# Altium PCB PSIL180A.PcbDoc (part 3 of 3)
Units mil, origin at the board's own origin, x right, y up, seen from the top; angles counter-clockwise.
Board outline 4350 x 4350 mil, 4 copper layers (L1-Top Layer, L2-GND, L3-GND/SIG, L4-Bottom Layer), stack 60.02 mil thick; 134 components, 52 nets, 287 pads, 1110 vias.
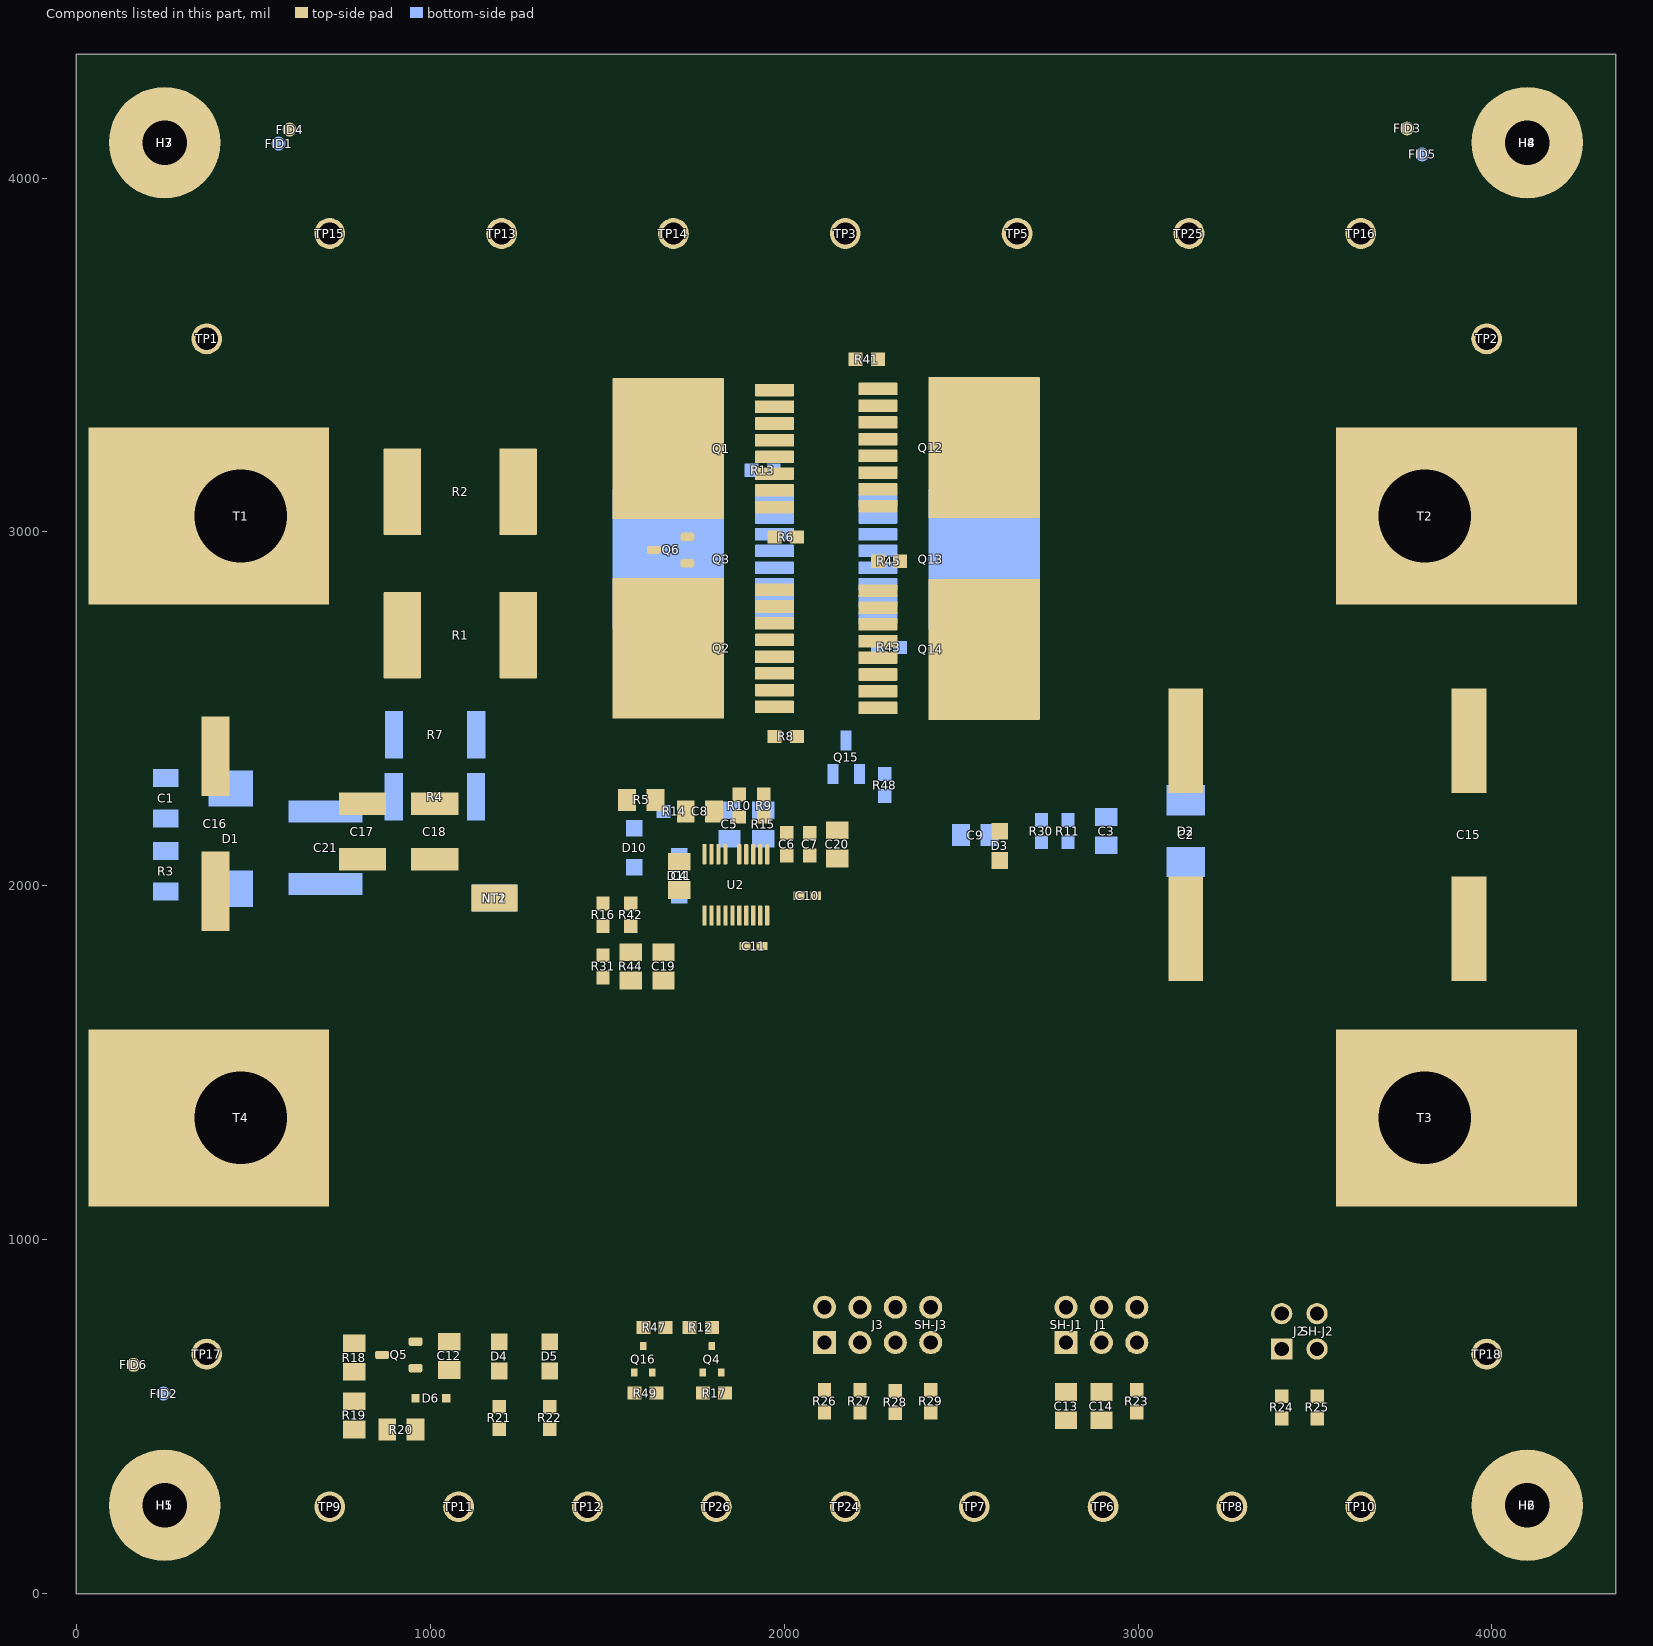
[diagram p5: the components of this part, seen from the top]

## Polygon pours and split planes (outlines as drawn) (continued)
GND on L4-Bottom Layer "L1-Top Layer-GND" (solid, remove dead copper, pour order 158): 4274.08,893.13 4318.92,848.29 4318.92,100.57 4256.14,37.79 1954.09,37.79 135.88,37.79 47.55,126.12 47.55,816.08 124.6,893.13
GND on L4-Bottom Layer "L2-GND-GND 1" (solid, remove dead copper, pour order 42): 1229.29,1736.51 1229.29,1908.33 1208.39,1929.23 1208.39,2001.67 1229.29,2022.57 1229.29,2105.78 1275.44,2151.93 1509.75,2151.93 1527.77,2133.91 1527.77,2027.73 1618.65,1936.85 1745.14,1936.85 1798.97,1990.68 1798.97,2147.17 1818.65,2167.01 1879.17,2167.01 1897.46,2148.72 1897.46,2106.89 1952.45,2051.9 2317.87,2051.9 2372.25,2106.28 2372.25,2175.91 2380.57,2184.23 2482.44,2184.23 2514.74,2151.93 2514.74,1788.89 2345.54,1619.69 1346.11,1619.69
PGND on L2-GND "L2-GND-GND 2" (solid, remove dead copper, pour order 208): 4244.3,2180.52 2596,2180.52 2571.47,2155.99 2571.47,1686.32 3327.83,929.96 4267.68,929.96 4316.91,979.19 4316.91,2107.91
GND on L2-GND "L2-GND-GND" (solid, remove dead copper, pour order 206): 1229.29,2120.26 1229.29,1012.12 1110.07,892.9 124.37,892.9 47.55,816.08 47.55,126.12 135.88,37.79 4256.14,37.79 4318.92,100.57 4318.92,848.29 4274.08,893.13 3278.15,893.13 2514.74,1656.54 2514.74,2150.38 2484.89,2180.23 2363.52,2180.23 2263.85,2080.56 1785.16,2080.56 1648.83,1944.23 1619.01,1944.23 1597.84,1965.4 1597.84,2161.01 1578.62,2180.23 1289.26,2180.23
no net on L2-GND "L2-GND-No Net" (solid, remove dead copper, pour order 204): 1382.07,2094.92
NetQ15_3 on L2-GND "L2-GND-NetQ15_5" (solid, remove dead copper, pour order 182): 1283.87,2409.16 1182.12,2409.16 1155.82,2382.86 1155.82,2229.86 1174.86,2210.96 1963.29,2210.96 2004.8,2252.47 2004.8,2314.47 2030.72,2340.39 2140.03,2340.39 2167.18,2367.54 2167.18,2458.44 2148.33,2477.29 1870.09,2477.29 1801.96,2409.16
VIN on L2-GND "L1-Top Layer-VIN" (solid, remove dead copper, pour order 180): 966.32,2209.69 1033.92,2277.29 1033.92,3466.52 897.93,3602.51 92.44,3602.51 33.33,3543.4 33.33,2273.62 97.26,2209.69 146.95,2209.69 153.96,2202.68 172.22,2202.68 179.43,2209.69 467.81,2209.69
CS- on L2-GND "L1-Top Layer-CS-" (solid, remove dead copper, pour order 178): 1148.84,2503.42 1148.84,3550.99 1054.75,3645.08 92.7,3645.08 33.33,3704.45 33.33,4226.37 121.63,4314.67 2747.98,4314.67 2824.14,4238.51 2824.14,3679.98 2753.48,3609.32 2003.28,3609.32 1878.79,3484.83 1878.79,2526.63 1795,2444.06 1208.2,2444.06
VOUT on L2-GND "L1-Top Layer-VOUT 1" (solid, remove dead copper, pour order 176): 2374.5,2241.54 2386.05,2253.09 2386.05,3519.16 2449.22,3582.33 2764.55,3582.33 2851.07,3668.85 2851.07,4246.52 2916.44,4311.89 4236.52,4311.89 4316.07,4232.34 4316.07,2277.74 4247.12,2208.79 2411.97,2208.79 2392.58,2228.5 2379.78,2228.5 2374.5,2233.78
SRC on L2-GND "L1-Top Layer-VIN" (solid, remove dead copper, pour order 138): 2152.33,2323.24 2185.31,2356.22 2185.31,2466.32 2156.89,2495.12 1943.44,2495.12 1910.92,2527.64 1910.92,3426.1 1927.58,3442.75 2298.85,3442.75 2361.38,3380.22 2361.29,2252.16 2246.25,2137.12 2038.48,2137.12 2023.93,2151.67 2023.93,2309.25 2037.92,2323.24
PGND on L2-GND "L1-Top Layer-PGND 1" (solid, remove dead copper, pour order 172): 1036.54,2180.52 1142.08,2074.98 1142.08,1080.24 991.8,929.96 131.98,929.96 33.33,1028.61 33.33,2081.38 132.47,2180.52
VOUT on L3-GND/SIG "L3-GND/SIG-VOUT" (solid, pour order 196): 3300.64,971.83 2641.74,971.83 2234.07,1379.5 2234.07,1999.37 2363.43,2128.73 2363.43,2329.59 2384.56,2351.3 2384.56,2479.18 2458.13,2552.75 2458.13,3076.46 2388.65,3145.94 2388.65,3559.57 2449.24,3620.16 4051.32,3620.16 4302.95,3368.53 4302.95,101.16 4239.02,37.23 3727.29,37.23 3679.56,84.96 3679.56,706.75 3537.69,848.62 3423.85,848.62
SRC on L3-GND/SIG "L3-GND/SIG-SRC 1" (solid, pour order 192): 2041.93,2780.57 2030.86,2769.5 2030.86,2561.32 2088.86,2503.32 2200.89,2503.32 2229.31,2531.74 2229.31,2763.73 2212.07,2780.97
SRC on L3-GND/SIG "L3-GND/SIG-SRC 2" (solid, pour order 190): 2040.19,3426.79 2031.26,3417.86 2031.26,3037.17 2106.57,2961.86 2106.57,2892.52 2120.3,2878.79 2223.96,2878.79 2258.25,2913.08 2258.25,3390.08 2221.7,3426.63
no net on L3-GND/SIG "L3-GND/SIG-No Net" (solid, pour order 188): 2649.11,3832.49
VIN on L3-GND/SIG "L3-GND/SIG-VIN" (solid, remove dead copper, pour order 186): 969.08,2233.38 1008.92,2233.38 1033.92,2258.38 1033.92,2285.42 1033.92,3466.52 897.57,3602.87 92.44,3602.51 31.88,3541.95 31.88,2277.94 76.44,2233.38
CS- on L3-GND/SIG "L1-Top Layer-CS-" (solid, remove dead copper, pour order 146): 1453.58,740.68 995.48,282.58 995.48,185.17 897.21,86.9 496.18,84.46 121.19,84.46 43.34,162.31 43.34,2078.48 128.22,2163.36 1038.24,2163.36 1148.84,2273.96 1148.84,2901.2 1148.84,3462.83 1239.13,3553.12 1802.9,3553.12 1839.68,3516.34 1839.68,3439.24 1650.14,3249.7 1650.14,2063.84 1650.24,1973.86 1453.58,1777.2

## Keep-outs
Keep-Out Layer:
  text ".Layer_Name" at -73,-825.99 h60

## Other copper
L1-Top Layer:
  pour cut-out: 160.36,708.74 cw(c160.36,648.74) 220.36,648.74 cw(c160.36,648.74) 160.36,588.74 cw(c160.36,648.74) 100.36,648.74 cw(c160.36,648.74)
  pour cut-out: 3760.04,4200.03 cw(c3760.04,4140.03) 3820.04,4140.03 cw(c3760.04,4140.03) 3760.04,4080.03 cw(c3760.04,4140.03) 3700.04,4140.03 cw(c3760.04,4140.03)
  pour cut-out: 602.83,4077.04 cw(c602.83,4137.04) 542.83,4137.04 cw(c602.83,4137.04) 602.83,4197.04 cw(c602.83,4137.04) 662.83,4137.04 cw(c602.83,4137.04)
  region net VIN: 1602.33,2145.88 1612.28,2135.93 1628.38,2135.93 1635.68,2143.23 1635.68,2169.78 1628.32,2177.14 1608.95,2177.14 1602.32,2170.51
  region net DIODE: 1949.73,1947.45 1946.62,1944.34 1946.62,1869.6 1921.43,1844.41 1921.43,1817.93 1924.13,1815.23 1982.41,1815.23 1996.87,1829.69 1996.87,1943.36 1992.78,1947.45
  region net NetC19_1: 1695.04,1802.2 1695.04,1789.96 1692.2,1787.12 1534.82,1787.12 1532.53,1789.41 1532.53,1899.02 1541.25,1907.74 1603.55,1907.74 1641.88,1946.07 1778.98,1946.07 1780.97,1944.08 1780.97,1888.13
  region net GND: 2506.7,2180.23 2514.74,2172.19 2514.74,1864.95 2500.78,1850.99 2385.83,1850.99 2357.48,1879.34 2357.48,2156.1 2381.61,2180.23
  region net NetC4_1: 1762.41,2043.26 1673.57,2043.26 1672.49,2044.34 1672.49,2095.42 1698.14,2121.07 1777.12,2121.07 1780.96,2117.23 1780.96,2061.81
  pour cut-out: 2033.05,2392.05
  region net SRC: 1939.44,2162.71 1974.77,2162.71 2019.81,2207.74 2087.54,2207.74 2093.53,2201.76 2093.53,2131.32 2091.41,2129.29 1925.8,2129.29 1918.83,2122.32 1918.83,2061.95 1917.85,2060.97 1908.02,2060.97 1907.06,2061.93 1907.05,2130.32
  region net CS-: 1130.03,3127.1 1132.46,3124.67 1132.46,3112.73 1125.05,3105.32 1117.55,3105.32 1114.38,3108.49 1114.38,3124.32 1117.16,3127.1
  region net VIN: 1049.49,3127.1 1047.06,3124.67 1047.06,3112.73 1054.47,3105.32 1061.97,3105.32 1065.14,3108.49 1065.14,3124.32 1062.36,3127.1
  region: 1848.83,2930.39
  region net CS-: 1123.13,2702.97 1123.13,2697.63 1117.55,2692.05 1099.77,2692.05 1098.62,2693.2 1098.62,2725.27 1101.18,2727.83 1115.52,2727.83 1123.13,2720.22
  region net VIN: 1052.05,2714.88 1052.05,2720.22 1057.63,2725.8 1075.41,2725.8 1076.56,2724.65 1076.56,2692.58 1074,2690.02 1059.66,2690.02 1052.05,2697.63
  region net GND: 2070.65,1983.87 2116,2029.22 2116,2101.34 2122.19,2107.53 2200.9,2107.53 2213.27,2095.16 2213.27,1937.9 2132.21,1857.86 2076.42,1857.86 2070.65,1863.63
  region: 755.75,652.2
  region net GND: 1879.45,1888.74 1879.45,1882.84 1890.67,1871.62 1890.75,1858.72 1907.72,1841.75 1907.72,1813.76 1899.88,1805.92 1868.67,1805.92 1859.85,1814.74 1859.85,1872.26 1867.72,1880.13 1867.72,1973.97 1859.41,1982.28 1837.04,1982.28 1813.83,1959.07 1758.54,1959.07 1674.95,1959.07 1670.69,1963.33 1670.69,2011.95 1674.5,2015.76 1758.09,2015.76 1775.39,1998.46 1802.17,1998.46 1816.05,2012.34 1867.36,2012.34 1879.45,2000.25
  region net GND: 2748.09,500.79 2764.56,519.01 2949.86,519.01 2965.61,534.76 3022.69,534.76 3036.47,520.98 3036.47,414.68 3024.94,403.14 2760.88,403.14 2748.09,415.94
  region net GND: 1053.23,504.21 1032.21,525.23 1032.21,596.1 1019.41,608.89 1019.41,656.13 1023.35,660.07 1085.38,660.07 1104.06,641.4 1104.06,512.08 1096.18,504.21
  region net GND: 2453.24,521.96 2461.12,514.09 2461.12,444.57 2447.8,430.43 2092.02,430.43 2079.23,443.22 2079.23,518.75 2097.73,535.74 2439.46,535.74
  region net GND: 3366.01,506.95 3373,517.78 3535.3,517.78 3546.13,506.95 3546.13,420.51 3538.08,412.46 3375.15,412.46 3366.01,421.6
  region: 2031.36,787.48
  text ".Layer_Name" at -73,-825.99 h60
L2-GND:
  text ".Layer_Name" at -73,-825.99 h60
L3-GND/SIG:
  region net GATE: 1991.7,2930.73 1986.53,2935.9 1969.29,2935.9 1964.65,2931.26 1956.31,2931.26 1951.24,2936.33 1923.39,2936.33 1914.08,2926.85 1914.08,2878.36 1898.54,2862.82 1898.54,2824.12 1903.26,2819.4 1912.11,2819.4 1918.18,2813.33 1918.18,2780.51 1923.11,2775.58 1939.94,2775.58 1947.63,2783.27 1947.63,2806.15 1955.97,2814.49 1969.43,2814.49 1985.93,2797.99 2009.55,2797.79 2020.09,2808.33 2020.09,2824.37 1998.43,2846.03 1998.43,2852.32 2003.9,2857.79 2003.9,2883.11 1991.7,2895.31
  region net GATE: 2156.71,2262.99
  text ".Layer_Name" at -70,-835.99 h60
L4-Bottom Layer:
  pour cut-out: 246.92,625.59 ccw(c246.92,565.59) 186.92,565.59 ccw(c246.92,565.59) 246.92,505.59 ccw(c246.92,565.59) 306.92,565.59 ccw(c246.92,565.59)
  pour cut-out: 3802.99,4126.92 ccw(c3802.99,4066.92) 3742.99,4066.92 ccw(c3802.99,4066.92) 3802.99,4006.92 ccw(c3802.99,4066.92) 3862.99,4066.92 ccw(c3802.99,4066.92)
  pour cut-out: 571.68,4037.21 ccw(c571.68,4097.21) 631.68,4097.21 ccw(c571.68,4097.21) 571.68,4157.21 ccw(c571.68,4097.21) 511.68,4097.21 ccw(c571.68,4097.21)
  text ".Layer_Name" at -73,-825.99 h60
Multi-Layer:
  pour cut-out: 1687.36,3749.34 cw(c1687.36,3843.34) 1593.36,3843.34 cw(c1687.36,3843.34) 1687.36,3937.34 cw(c1687.36,3843.34) 1781.36,3843.34 cw(c1687.36,3843.34)
  pour cut-out: 1201.8,3749.34 cw(c1201.8,3843.34) 1107.8,3843.34 cw(c1201.8,3843.34) 1201.8,3937.34 cw(c1201.8,3843.34) 1295.8,3843.34 cw(c1201.8,3843.34)
  pour cut-out: 716.24,3749.34 cw(c716.24,3843.34) 622.24,3843.34 cw(c716.24,3843.34) 716.24,3937.34 cw(c716.24,3843.34) 810.24,3843.34 cw(c716.24,3843.34)
  pour cut-out: 3629.6,3749.34 cw(c3629.6,3843.34) 3535.6,3843.34 cw(c3629.6,3843.34) 3629.6,3937.34 cw(c3629.6,3843.34) 3723.6,3843.34 cw(c3629.6,3843.34)
  pour cut-out: 3915,250 ccw(c4100,250) 4100,65 ccw(c4100,250) 4285,250 ccw(c4100,250) 4100,435 ccw(c4100,250)
  pour cut-out: 3915,4100 ccw(c4100,4100) 4100,3915 ccw(c4100,4100) 4285,4100 ccw(c4100,4100) 4100,4285 ccw(c4100,4100)
  pour cut-out: 65,250 ccw(c250,250) 250,65 ccw(c250,250) 435,250 ccw(c250,250) 250,435 ccw(c250,250)
  pour cut-out: 65.73,4102.58 ccw(c250.73,4102.58) 250.73,3917.58 ccw(c250.73,4102.58) 435.73,4102.58 ccw(c250.73,4102.58) 250.73,4287.58 ccw(c250.73,4102.58)

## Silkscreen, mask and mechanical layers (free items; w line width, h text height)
Top Overlay:
  drawing of 50 lines, arcs and shapes, not listed
  text "VIN" at 534.62,3375.26 h60
  text "VOUT" at 3634.96,3375.67 h60
  text "Max current 50A" at 49.31,2676 h50
  text "Max current 50A" at 3507.94,2676 h50
  text "11" at 1923.67,2124.51 h35
  text "20" at 1704.55,2121.27 h35
  text "10" at 1981.07,1864.1 h35
  text "Max current 50A" at 49.31,1678.37 h50
  text "Max current 50A" at 3507.94,1642.29 h50
  text "'.PRJ_Title'" at 1318.46,1489.55 h70
  text "'.PRJ_Number''.PCB_Rev'" at 1318.46,1371.02 h70
  text "TMR" at 2872.34,877.69 h35
  text "IWRN" at 2190.74,875.76 h35
  text "PGND" at 263.93,873.59 h60
  text "IMON" at 3404.39,867.73 h35
  text "PGND" at 3822.51,855.14 h60
  text "FLT_I/" at 1272.78,577.46 h30 r90
  text "FLT_T/" at 1415.81,577.46 h30 r90
  text ".Layer_Name" at -73,-825.99 h60
Bottom Overlay:
  region: 2213.65,2282.14 2236.91,2258.88 2190.45,2258.88
  text ".Layer_Name" at -73,-825.99 h60
Top Paste:
  text ".Layer_Name" at -73,-825.99 h60
Bottom Paste:
  text ".Layer_Name" at -73,-825.99 h60
Top Solder:
  text ".Layer_Name" at -73,-825.99 h60
  text ".Layer_Name" at -73,-825.99 h60
Bottom Solder:
  text ".Layer_Name" at -73,-825.99 h60
Drill Guide:
  text ".Layer_Name" at -73,-825.99 h60
M1 Board Outline:
  the board outline again, w10
  text ".Layer_Name" at -62,-837.5 h60
M2 Board Dimensions:
  rectangle: -525,-367.5 -150,-242.5
  rectangle: -650,-242.5 -525,-117.5
  lines w7: -650,-242.5 350,-242.5 ; -525,-367.5 -525,-117.5 ; -400,-367.5 -400,-117.5 ; -150,-367.5 -150,-117.5 ; 100,-367.5 100,-117.5 ; -650,-367.5 -650,-117.5 350,-117.5 350,-367.5 -650,-367.5
  text ".Layer_Name" at -70,-835.99 h60
M3 3D STEP Top:
  text ".Layer_Name" at -73,-825.99 h60
M4 3D STEP Bottom:
  text ".Layer_Name" at -73,-825.99 h60
M5 Assembly Top:
  lines w10: -942,-897.67 5658,-897.67 ; -942,-694.33 5660,-694.33 ; -942,-491 -942,-1101 3063,-1101 5660,-1101 5660,-491 -941.5,-491 -941.5,-1101 634,-1101 ; 1523,-1101 1523,-491 ; 2790,-694.33 2790,-491 ; 3630,-694.33 3630,-491 ; 4252,-1107.5 4252,-904.67
  text "COMPONENTS MARKED 'DNP' SHOULD NOT BE POPULATED." at 503.5,-286 h60
  text "ASSEMBLY VARIANT:" at 503,-401.5 h60
  text ".VariantName" at 1539,-401.5 h60
  text "PCB VIEWED FROM TOP SIDE" at -878.5,-623.17 h60
  text "BOARD #:" at 1598,-623.17 h60
  text ".PRJ_Number" at 2143.5,-623.17 h60
  text "REV:" at 2988,-623.17 h60
  text ".PCB_Rev" at 3279.5,-623.17 h60
  text "SVN REV:" at 3826,-623.17 h60
  text ".VersionControl_RevNumber" at 4332,-623.17 h60
  text "'.Layer_Name'" at 175,-822.5 h60
  text "TID #:" at 1598,-826.5 h60
  text ".TID" at 2143.5,-826.5 h60
  text "PLOT NAME =" at -878.5,-1031.84 h60
  text ".plot_File_Name" at -73,-1031.84 h60
  text "GENERATED    :" at 1600,-1031.84 h60
  text ".Print_Date" at 2469.5,-1031.84 h60
  text ".Print_Time" at 3198.5,-1031.84 h60
  text "TEXAS INSTRUMENTS" at 4463,-1031.84 h60
M6 Assembly Bottom:
  lines w10: -942.5,-694.83 5659.5,-694.83 ; -940.5,-898.17 5659.5,-898.17 ; 465.5,-1108 465.5,-905.17 ; 1087.5,-694.83 1087.5,-491.5 ; 1927.5,-694.83 1927.5,-491.5 ; 3194.5,-1101.5 3194.5,-491.5 ; 4083.5,-1101.5 5659,-1101.5 5659,-491.5 -942.5,-491.5 -942.5,-1101.5 1654.5,-1101.5 5659.5,-1101.5 5659.5,-491.5
  text "COMPONENTS MARKED 'DNP' SHOULD NOT BE POPULATED." at 5452,-285.5 h60
  text ".VariantName" at 4408,-401.5 h60
  text "ASSEMBLY VARIANT:" at 5447,-401.5 h60
  text ".VersionControl_RevNumber" at 385.5,-623.67 h60
  text "SVN REV:" at 891.5,-623.67 h60
  text ".PCB_Rev" at 1438,-623.67 h60
  text "REV:" at 1729.5,-623.67 h60
  text ".PRJ_Number" at 2574,-623.67 h60
  text "BOARD #:" at 3119.5,-623.67 h60
  text "PCB VIEWED FROM BOTTOM SIDE" at 5596,-623.67 h60
  text ".TID" at 2574,-827 h60
  text "TID #:" at 3119.5,-827 h60
  text "'.Layer_Name'" at 4679,-843.5 h60
  text "TEXAS INSTRUMENTS" at 254.5,-1032.34 h60
  text ".Print_Time" at 1519,-1032.34 h60
  text ".Print_Date" at 2248,-1032.34 h60
  text "GENERATED    :" at 3117.5,-1032.34 h60
  text ".plot_File_Name" at 4790.5,-1032.34 h60
  text "PLOT NAME =" at 5596,-1032.34 h60
M9 Title Sheet:
  drawing of 57 lines, arcs and shapes, not listed
  text "1" at 89.84,8069 h70
  text "2" at 2585.5,8069 h70
  text "3" at 5074.84,8069 h70
  text "4" at 7581.51,8069 h70
  text "5" at 10080.5,8069 h70
  text "6" at 12585.5,8069 h70
  text "A" at -1066.5,6926 h70
  text "A" at 13733.5,6926 h70
  text "B" at -1066.5,4546 h70
  text "B" at 13733.5,4546 h70
  text "C" at -1066.5,2171 h70
  text "C" at 13733.5,2171 h70
  text "PROJECT TITLE:" at 10693.5,310 h45
  text ".PRJ_Title" at 10743.5,176.67 h70
  text "DESIGNED FOR:" at 10693.5,9 h45
  text ".PRJ_Customer" at 10743.5,-131 h70
  text "D" at -1066.5,-199 h70
  text "D" at 13733.5,-199 h70
  text "FILE NAME:" at 10693.5,-291 h45
  text ".PRJ_Title" at 10743.5,-411 h70
  text "Texas Instruments (TI) and/or its licensors do not warrant the accuracy or completeness of this specification" at 5724,-572.84 h45
  text "ENGINEER:" at 10693.5,-581 h45
  text "LAYOUT BY:" at 12198.5,-581 h45
  text "or any information contained therein. TI and/or its licensors do not warrant that this design will meet" at 5679.02,-685.5 h45
  text "PACTRON" at 12258.96,-712.72 h70
  text ".PRJ_Engineer" at 10743.5,-735.99 h70
  text ".PCB_Layout" at 12249,-735.99 h70
  text "the specifications, will be suitable for your application or fit for any particular purpose, or will operate in" at 5679.02,-798.17 h45
  text ".Layer_Name" at -70,-835.99 h60
  text "ALTIUM DESIGNER VERSION:" at 12198.5,-891 h45
  text "an implementation. TI and/or its licensors do not warrant that the design is production worthy. You should" at 5679.02,-910.83 h45
  text "completely validate and test your design implementation to confirm the system functionality for your application." at 5724,-1023.5 h45
  text ".print_Scale" at 10743.5,-1024.33 h70
  text ".Application_BuildNumber" at 12249,-1024.33 h70
  text "1" at 89.84,-1231 h70
  text "2" at 2585.5,-1231 h70
  text "3" at 5074.84,-1231 h70
  text "4" at 7581.51,-1231 h70
  text "5" at 10080.5,-1231 h70
  text "6" at 12585.5,-1231 h70
M10 Fab Notes:
  drawing of 173 lines, arcs and shapes, not listed
  text "DESIGN INFORMATION" at 11728.02,6233.5 h60
  text "MIN. TRACK WIDTH:" at 11083.46,6053.5 h60
  text "MIL" at 12334.46,6053.5 h60
  text "8" at 12157.01,6047.94 h60
  text "6" at 12155.17,5924.58 h60
  text "MIN. CLEARANCE:" at 11083.46,5921.5 h60
  text "MIL" at 12339.46,5918.5 h60
  text "20" at 12142,5791.5 h60
  text "MIN. VIA PAD SIZE:" at 11083.46,5789.5 h60
  text "MIL" at 12340,5787.5 h60
  text "0.127mm (5MIL)" at 11778.46,5647.79 h60
  text "MINIMUM ANNULAR RING" at 10754.23,5643.5 h60
  text "EXTERNAL" at 12486.46,5643.5 h60
  text "PER" at 10954.23,5525.5 h60
  text "IPC-D-275 CLASS 2 LEVEL C" at 11174.23,5525.5 h60
  text "MIL, HOLES" at 12662.46,5413.21 h60
  text "+/-" at 12270,5412.5 h60
  text "+/-" at 13124,5412.5 h60
  text "REGISTRATION TOLERANCES:" at 10754.23,5407.5 h60
  text "METAL" at 11954,5407.5 h60
  text "5" at 12530.2,5407.5 h60
  text "3" at 13363.2,5407.5 h60
  text "MIL" at 13479.46,5407.5 h60
  text "+/-" at 13124,5294.5 h60
  text "HOLE SIZE TOLERANCE (UNLESS OTHERWISE SPECIFIED):" at 10754.23,5289.5 h60
  text "3" at 13363.2,5289.5 h60
  text "MIL" at 13479.46,5289.5 h60
  text "MATERIAL:" at 10679.46,5080.04 h60
  text "Fab notes:" at 5219.41,5078.41 h90
  text "FR-4 High Tg" at 11665.9,4939.71 h60
  text "FR-408" at 11100.46,4931.14 h60
  text "OTHER" at 12588.46,4931.14 h60
  text "1. NO VENDOR LOGO OR NAME ON THE BOARD." at 5393.9,4927.97 h70
  text "X" at 11511,4927.5 h60
  text "62 MIL (1.6mm) +/-10%" at 11420.56,4768.42 h60
  text "THICKNESS:" at 10754.23,4764.14 h60
  text "X" at 11292.4,4764.14 h60
  text "OTHER" at 12705.46,4764.14 h60
  text "2. ALL HOLES SHOULD BE FHS." at 5393.9,4752.15 h70
  text "TOLERANCE:" at 10754.23,4606.14 h60
  text "X" at 11593.54,4606.14 h60
  text "ANSI IPC-6012 TYPE 3 CLASS 2" at 11780.48,4606.14 h60
  text "3. NEED TO REMOVE THE NON FUNCTIONAL PADS IN INNER LAYERS." at 5393.9,4576.32 h70
  text "OTHER +/-" at 11780.46,4450.14 h60
  text "4. CLIP SILKSCREEN ON NO MASK AREA." at 5393.9,4398.87 h70
  text "BOW & TWIST:" at 10754.23,4293.14 h60
  text "X" at 11593.54,4293.14 h60
  text "ANSI IPC-6012 TYPE 3 CLASS 2" at 11780.48,4293.14 h60
  text "OTHER +/-" at 11780.46,4134.63 h60
  text "DRILLING:" at 10679.46,3996.14 h60
  text "REFERENCE:" at 10754.23,3879.14 h60
  text "X" at 11402.46,3879.14 h60
  text "AS SHOWN" at 11589.46,3879.14 h60
  text "X" at 12303.46,3879.14 h60
  text "NC_DRILL FILES" at 12440.46,3879.14 h60
  text "PTH COPPER THICKNESS:" at 10754.23,3721.14 h60
  text "X" at 11884.46,3721.14 h60
  text "20-30 um" at 12021.46,3721.14 h60
  text "OTHER" at 12738.46,3721.14 h60
  text "BOARD FINISH:" at 10679.46,3562.14 h60
  text "SILKSCREEN:" at 10834.68,3444.14 h60
  text "X" at 11783.46,3444.14 h60
  text "TOP" at 11909.46,3444.14 h60
  text "X" at 12293.46,3444.14 h60
  text "BOTTOM" at 12420.46,3444.14 h60
  text "SILKSCREEN COLOR:" at 10834.68,3277.14 h60
  text "X" at 11782.42,3277.14 h60
  text "WHITE" at 11909.46,3277.14 h60
  text "OTHER" at 12420.46,3277.14 h60
  text "X" at 11913.42,3117.94 h60
  text "GREEN" at 12040.46,3117.94 h60
  text "OTHER" at 12658.46,3117.94 h60
  text "SOLDER RESIST COLOR:" at 10834.68,3107.14 h60
  text "X" at 11913.42,2947.94 h60
  text "MATTE" at 12040.46,2947.94 h60
  text "SEMI-GLOSS" at 12658,2947.3 h60
  text "IMMERSION GOLD (ENIG)" at 11740.46,2759.42 h60
  text "ENEPIG" at 13078,2756.14 h60
  text "SURFACE FINISH:" at 10679.46,2755.14 h60
  text "X" at 11553.52,2755.14 h60
  text "IMM. TIN/SILVER OR EQUIV" at 11009,2598.14 h60
  text "OTHER" at 12440.46,2598.14 h60
  text "ARRAY/PANEL:" at 10679.46,2419.14 h60
  text "X" at 11553.52,2414.85 h60
  text "CUT AND TRIM PER M1 BOARD OUTLINE" at 11740.46,2414.85 h60
  text "N.C. ROUTE" at 11740.46,2263.14 h60
  text "V. SCORE" at 12606.46,2263.14 h60
  text "CERTIFICATION:" at 10679.46,2126.14 h60
  text "MATERIALS AND WORKMANSHIP FOR ALL PCBS" at 11404.46,2126.14 h60
  text "TO MEET OR EXCEED THE REQUIREMENTS OF:" at 11404.46,2028.14 h60
  text "X" at 11030.96,1891.63 h60
  text "ANSI IPC-A-600F CLASS ->" at 11169.96,1891.63 h60
  text "X" at 12809.02,1891.63 h60
  text "2" at 12927.96,1891.64 h60
  text "1" at 12612.96,1890.14 h60
  text "3" at 13281.96,1890.14 h60
  text "X" at 11845.02,1732.14 h60
  text "RoHS" at 11981.96,1732.14 h60
  text "OTHER" at 12626.37,1732.14 h60
  text "PER ORDER" at 13023.42,1732.14 h60
  text "ALL BOARDS MUST MEET OR EXCEED UL94-V0 REQUIREMENTS." at 10707,1566.5 h60
  text "PCB MUST BEAR THE UL94V-0 UL REGISTERED MATERIAL ID NUMBER" at 10707,1446.5 h60
  text "ADDITIONAL REQUIREMENTS:" at 10679.46,1273.14 h60
  text "MICROSECTION:" at 10754.23,1158.14 h60
  text "YES" at 11659.96,1158.14 h60
  text "REQUIRED" at 12521.46,1001.99 h60
  text "BARE BOARD ELEC. TEST:" at 10754.23,999.14 h60
  text "NONE" at 12059.96,999.14 h60
  text "X" at 12394.46,999.14 h60
  text "PER ORDER" at 13113.46,999.14 h60
  text ".Layer_Name" at -70,-835.99 h60
M11 Gerber Information:
  circle w10: c-284.34,4853.75 r39.57
  circle w10: c-284.34,4854.38 r72.22
  circle w10: c4650.6,4853.75 r39.57
  circle w10: c4650.6,4854.38 r72.22
  circle w10: c4625.58,-191.48 r72.22
  circle w10: c4625.58,-192.11 r39.57
  lines w10: -942,-897.67 5658,-897.67 ; -942,-694.33 5660,-694.33 ; -942,-491 -942,-1101 3063,-1101 5660,-1101 5660,-491 -941.5,-491 -941.5,-1101 634,-1101 ; -383.78,4854.98 -283.78,4854.98 ; -283.78,4754.98 -283.78,4854.98 ; -283.78,4954.98 -283.78,4854.98 ; -183.78,4854.98 -283.78,4854.98 ; 1523,-963.73 1523,-491 ; 2790,-694.33 2790,-491 ; 3630,-694.33 3630,-491 ; 4252,-1107.5 4252,-904.67 ; 4526.14,-190.88 4626.14,-190.88 ; 4551.16,4854.98 4651.16,4854.98 ; 4626.14,-290.88 4626.14,-190.88 ; 4626.14,-90.88 4626.14,-190.88 ; 4651.16,4754.98 4651.16,4854.98 ; 4651.16,4954.98 4651.16,4854.98 ; 4726.14,-190.88 4626.14,-190.88 ; 4751.16,4854.98 4651.16,4854.98
  text "ALL ARTWORK VIEWED FROM TOP SIDE" at -878.5,-623.17 h60
  text "BOARD #:" at 1598,-623.17 h60
  text ".PRJ_Number" at 2143.5,-623.17 h60
  text "REV:" at 2988,-623.17 h60
  text ".PCB_Rev" at 3279.5,-623.17 h60
  text "SVN REV:" at 3826,-623.17 h60
  text ".VersionControl_RevNumber" at 4332,-623.17 h60
  text "LAYER NAME =" at -878.5,-825.99 h60
  text "TID #:" at 1598,-826.5 h60
  text ".TID" at 2143.5,-826.5 h60
  text "GENERATED    :" at 1595.28,-978.66 h60
  text ".Print_Date" at 2464.78,-978.66 h60
  text ".Print_Time" at 3193.78,-978.66 h60
  text "PLOT NAME =" at -878.5,-1031.84 h60
  text "TEXAS INSTRUMENTS" at 4463,-1031.84 h60
  text ".plot_File_Name" at -181.81,-1067.54 h60
M12 Stackup:
  drawing of 307 lines, arcs and shapes, not listed
  text "Stack-up:" at 5188.77,3893.7 h90
  text "Layer" at 5272.97,3722.43 h50
  text "Name" at 5613.9,3722.43 h50
  text "Material" at 6438,3722.43 h50
  text "Thickness" at 7153.8,3722.43 h50
  text "Constant" at 7694.67,3722.43 h50
  text "Board Layer Stack" at 8168.88,3722.43 h50
  text "1" at 5272.97,3622.43 h50
  text "Top Overlay" at 5613.9,3622.43 h50
  text "2" at 5272.97,3522.43 h50
  text "Top Solder" at 5613.9,3522.43 h50
  text "Solder Resist" at 6438,3522.43 h50
  text "1.00mil" at 7153.8,3522.43 h50
  text "3.5" at 7694.67,3522.43 h50
  text "2 OZ (COPPER + PLATING)" at 9172.77,3424.08 h50
  text "3" at 5272.97,3422.43 h50
  text "L1-Top Layer" at 5613.9,3422.43 h50
  text "Copper" at 6438,3422.43 h50
  text "2.76mil" at 7153.8,3422.43 h50
  text "4" at 5272.97,3322.43 h50
  text "Dielectric 1" at 5613.9,3322.43 h50
  text "FR-4 High Tg" at 6438,3322.43 h50
  text "10.62mil" at 7153.8,3322.43 h50
  text "4.13" at 7694.67,3322.43 h50
  text "2 OZ" at 9172.77,3224.08 h50
  text "5" at 5272.97,3222.43 h50
  text "L2-GND" at 5613.9,3222.43 h50
  text "Copper" at 6438,3222.43 h50
  text "2.64mil" at 7153.8,3222.43 h50
  text "6" at 5272.97,3122.43 h50
  text "Dielectric 2" at 5613.9,3122.43 h50
  text "FR-4 High Tg" at 6438,3122.43 h50
  text "28.00mil" at 7153.8,3122.43 h50
  text "4.53" at 7694.67,3122.43 h50
  text "2 OZ" at 9172.77,3024.08 h50
  text "7" at 5272.97,3022.43 h50
  text "L3-GND/SIG" at 5613.9,3022.43 h50
  text "Copper" at 6438,3022.43 h50
  text "2.64mil" at 7153.8,3022.43 h50
  text "8" at 5272.97,2922.43 h50
  text "Dielectric 3" at 5613.9,2922.43 h50
  text "FR-4 High Tg" at 6438,2922.43 h50
  text "10.62mil" at 7153.8,2922.43 h50
  text "4.13" at 7694.67,2922.43 h50
  text "2 OZ (COPPER + PLATING)" at 9172.77,2824.08 h50
  text "9" at 5272.97,2822.43 h50
  text "L4-Bottom Layer" at 5613.9,2822.43 h50
  text "Copper" at 6438,2822.43 h50
  text "2.76mil" at 7153.8,2822.43 h50
  text "10" at 5272.97,2722.43 h50
  text "Bottom Solder" at 5613.9,2722.43 h50
  text "Solder Resist" at 6438,2722.43 h50
  text "1.00mil" at 7153.8,2722.43 h50
  text "3.5" at 7694.67,2722.43 h50
  text "11" at 5272.97,2622.43 h50
  text "Bottom Overlay" at 5613.9,2622.43 h50
  text ".Layer_Name" at -70,-835.99 h60
M13 Component Bodies Top:
  text ".Layer_Name" at -73,-825.99 h60
M14 Component Bodies Bottom:
  text ".Layer_Name" at -73,-825.99 h60
M15 Courtyards Top:
  text ".Layer_Name" at -73,-825.99 h60
M16 Courtyards Bottom:
  text ".Layer_Name" at -73,-825.99 h60
Drill Drawing:
  circle w6: c5280.12,1686.28 r22.22
  circle w6: c5280.12,1586.28 r13.33
  circle w6: c5280.12,1586.28 r22.22
  lines w6: 5257.89,1164.06 5302.34,1164.06 5302.34,1208.5 5257.89,1208.5 5257.89,1164.06 ; 5257.89,1286.28 5280.12,1264.06 5302.34,1286.28 5280.12,1308.5 5257.89,1286.28 ; 5257.89,1375.17 5269.01,1375.17 5280.12,1364.06 5291.23,1375.17 5302.34,1375.17 5291.23,1386.28 5302.34,1397.39 5291.23,1397.39 5280.12,1408.5 5269.01,1397.39 5257.89,1397.39 5269.01,1386.28 5257.89,1375.17 ; 5257.89,1508.5 5302.34,1508.5 5280.12,1464.06 5257.89,1508.5 ; 5257.89,1764.06 5257.89,1775.17 5269.01,1786.28 5257.89,1797.39 5257.89,1808.5 5269.01,1808.5 5280.12,1797.39 5291.23,1808.5 5302.34,1808.5 5302.34,1797.39 5291.23,1786.28 5302.34,1775.17 5302.34,1764.06 5291.23,1764.06 5280.12,1775.17 5269.01,1764.06 5257.89,1764.06
  lines w12: 5218.24,1134.06 9002.25,1134.06 ; 5218.24,1834.06 9002.25,1834.06 ; 5583.36,1034.06 5583.36,1934.06 ; 6008.58,1034.06 6008.58,1934.06 ; 6860.33,1034.06 6860.33,1934.06 ; 7195.44,1034.06 7195.44,1934.06 ; 8427.07,1034.06 8427.07,1934.06 ; 5218.24,1034.06 9002.25,1034.06 9002.25,1934.06 5218.24,1934.06 5218.24,1034.06
  text "Drill Table:" at 5122.82,2069.81 h90
  text "Symbol" at 5278.24,1864.06 h48
  text "Count" at 5613.36,1864.06 h48
  text "Hole Size" at 6038.58,1864.06 h48
  text "Plated" at 6890.33,1864.06 h48
  text "Drill Layer Pair" at 7225.44,1864.06 h48
  text "Tolerance" at 8457.07,1864.06 h48
  text "15" at 5613.36,1764.06 h40
  text "10.00mil (0.25400mm)" at 6038.58,1764.06 h40
  text "PTH" at 6890.33,1764.06 h40
  text "L1-Top Layer - L4-Bottom Layer" at 7225.44,1764.06 h40
  text "+3mil / -3mil" at 8457.07,1764.06 h40
  text "863" at 5613.36,1664.06 h40
  text "12.00mil (0.30480mm)" at 6038.58,1664.06 h40
  text "PTH" at 6890.33,1664.06 h40
  text "L1-Top Layer - L4-Bottom Layer" at 7225.44,1664.06 h40
  text "+3mil / -3mil" at 8457.07,1664.06 h40
  text "232" at 5613.36,1564.06 h40
  text "16.00mil (0.40640mm)" at 6038.58,1564.06 h40
  text "PTH" at 6890.33,1564.06 h40
  text "L1-Top Layer - L4-Bottom Layer" at 7225.44,1564.06 h40
  text "+3mil / -3mil" at 8457.07,1564.06 h40
  text "18" at 5613.36,1464.06 h40
  text "40.00mil (1.01600mm)" at 6038.58,1464.06 h40
  text "PTH" at 6890.33,1464.06 h40
  text "L1-Top Layer - L4-Bottom Layer" at 7225.44,1464.06 h40
  text "+3mil / -3mil" at 8457.07,1464.06 h40
  text "20" at 5613.36,1364.06 h40
  text "63.00mil (1.60020mm)" at 6038.58,1364.06 h40
  text "PTH" at 6890.33,1364.06 h40
  text "L1-Top Layer - L4-Bottom Layer" at 7225.44,1364.06 h40
  text "+3mil / -3mil" at 8457.07,1364.06 h40
  text "4" at 5613.36,1264.06 h40
  text "125.98mil (3.19999mm)" at 6038.58,1264.06 h40
  text "NPTH" at 6890.33,1264.06 h40
  text "L1-Top Layer - L4-Bottom Layer" at 7225.44,1264.06 h40
  text "+2mil / -2mil" at 8457.07,1264.06 h40
  text "4" at 5613.36,1164.06 h40
  text "262.00mil (6.65480mm)" at 6038.58,1164.06 h40
  text "PTH" at 6890.33,1164.06 h40
  text "L1-Top Layer - L4-Bottom Layer" at 7225.44,1164.06 h40
  text "+3mil / -3mil" at 8457.07,1164.06 h40
  text "1156 Total" at 5613.36,1064.06 h40
  text ".Layer_Name" at -73,-825.99 h60
M17 Embedded Cavity:
  text ".Layer_Name" at -73,-825.99 h60
M18 Embedded Assembly:
  text ".Layer_Name" at -73,-825.99 h60
M19 Embedded Keepout:
  text ".Layer_Name" at -73,-825.99 h60
Mechanical 20:
  text "1)ALL VIAS ARE TENTED, UNLESS SOLDERMASK EXPOSED" at 5090.08,6447.55 h85
  text "2)COPPER THICKNESS IS 2OZ." at 5090,6433.5 h85
  text "3)THIS IS NOT AN IMPEDANCE CONTROLLED BOARD." at 5087,6342.5 h85
  text "4)VENDOR MAY ADJUST SOLDERMAK WHEREVER THE SOLDERMASK PADS ARE SAME SIZE(1:1)" at 5080,6244.5 h85
  text "AS PER THE MANUFACTURING CAPABILITIES AND ALL OTHER SOLDERMASK PADS SHALL NOT BE MODIFIED." at 5129.19,6142.55 h85
  text "PROVIDED NO ADJACENT COPPER IS EXPOSED AND NO CONFLICT IS PRODUCED WITH ANY STATED \"VIA TENTING/COVERING REQUIREMENTS\"." at 5132,6051.5 h85
  text "DRILL TOLERANCE:" at 6103,903.5 h40
  text "FOR PTH +/- 3MIL" at 6445.77,803.46 h40
  text "FOR NPTH +/- 2MIL" at 6445.77,714.87 h40
  text "7.874mil drill:+0/-7.874mil" at 6439.77,624.37 h40
  text "12mil drill:+0/-12mil" at 6444.77,533.86 h40
M21_Assembly_note:
  lines w10: -139.78,1278.87 -21.2,1345 ; -139.78,2978.87 -21.2,3045 ; -138.93,1418.69 -21.2,1345 ; -138.93,3118.69 -21.2,3045 ; -0.3,6596.97 -392.58,6596.97 -392.58,5390.71 1592.92,5390.71 1592.92,4665.98 ; 4563.93,1418.69 4446.2,1345 ; 4563.93,3118.69 4446.2,3045 ; 4564.78,1278.87 4446.2,1345 ; 4564.78,2978.87 4446.2,3045 ; -420.69,3045 -420.69,1345 -21.2,1345 ; -420.69,3045 -21.2,3045 ; -420.69,3045 -420.69,4666.47 4845.69,4666.47 4845.69,3045 ; 4446.2,1345 4845.69,1345 4845.69,3045 ; 4446.2,3045 4845.69,3045
  text "PLEASE MAKE SURE THE SOLDER DOES NOT FLOW INTO THE HOLES WHILE SOLDERING THE BELOW PARTS" at -321.63,6482.45 h60
  text "TOP SIDE : TERMINAL LUG SHOULD BE SOLDER WITH TOP SURFACE PLATED PADS AND DONOT SHOLDER NUT WITH TERMINAL LUG" at -321.63,6345.29 h60
  text "BOTTOM SIDE :  SCREW SHOULD BE SOLDER WITH BOTTOM SURFACE PLATED PADS. PLEASE MAKE SURE DONOT LOOSE THE SCREW AFTER SOLDER WITH PLATED PADS" at -321.63,6208.12 h60
  text "T1 TO T4 ( CB70-14-CY )" at -321.63,5954.68 h60
  text "H9 TO H12  MACHINE SCREW PAN SLOTTED 10-32 ( PMSSS 102 0050 PH )  INTALL BOTTOMSIDE OF THE T1 TO T4( CB70-14-CY )" at -321.63,5801.58 h60
  text "H13 TO H16  MACHINE SCREW NUT, HEX, 3/8', STN, STEEL, 10-32 ( HNSS 102 )  INTALL TOPSIDE OF THE T1 TO T4( CB70-14-CY )" at -321.63,5668.48 h60
  text "H17 TO H20 WASHER, SPLIT LOCK, #10 ( 1477 )  INTALL TOPSIDE OF THE T1 TO T4 ( CB70-14-CY )" at -321.63,5515.38 h60

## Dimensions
0,4350 to 4350,4350 on M2 Board Dimensions
-650,-367.5 to 350,-367.5 on M2 Board Dimensions
0,4350 to 0,0 on M2 Board Dimensions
